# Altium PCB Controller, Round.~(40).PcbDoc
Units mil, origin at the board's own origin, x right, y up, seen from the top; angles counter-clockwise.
Board outline 1800 x 1800 mil, 4 copper layers (Top Layer, MidLayer1, MidLayer2, Bottom Layer); 46 components, 54 nets, 215 pads, 50 vias.
Unrouted connection lines stored in the file: 29.
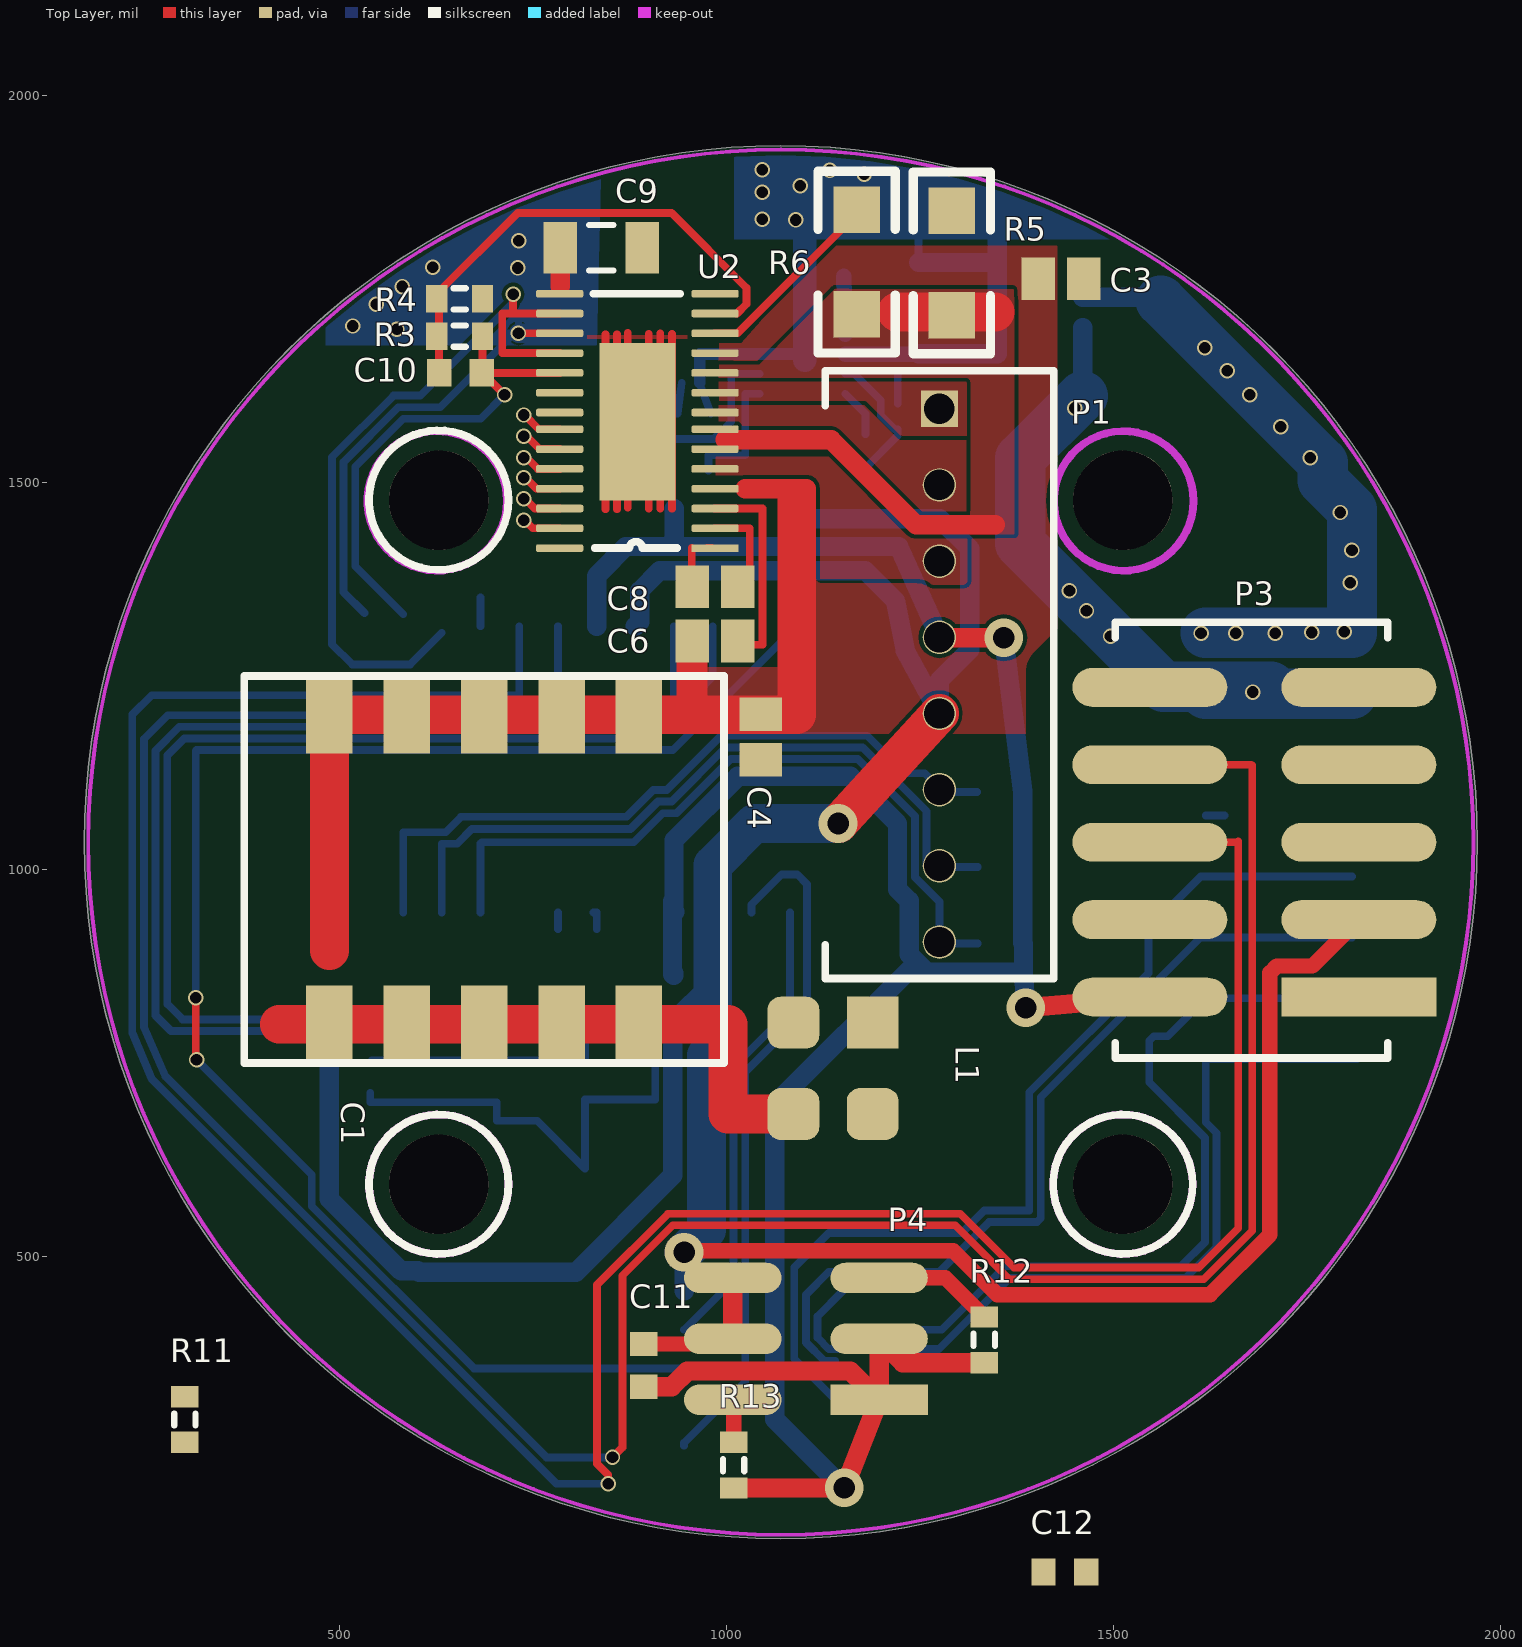
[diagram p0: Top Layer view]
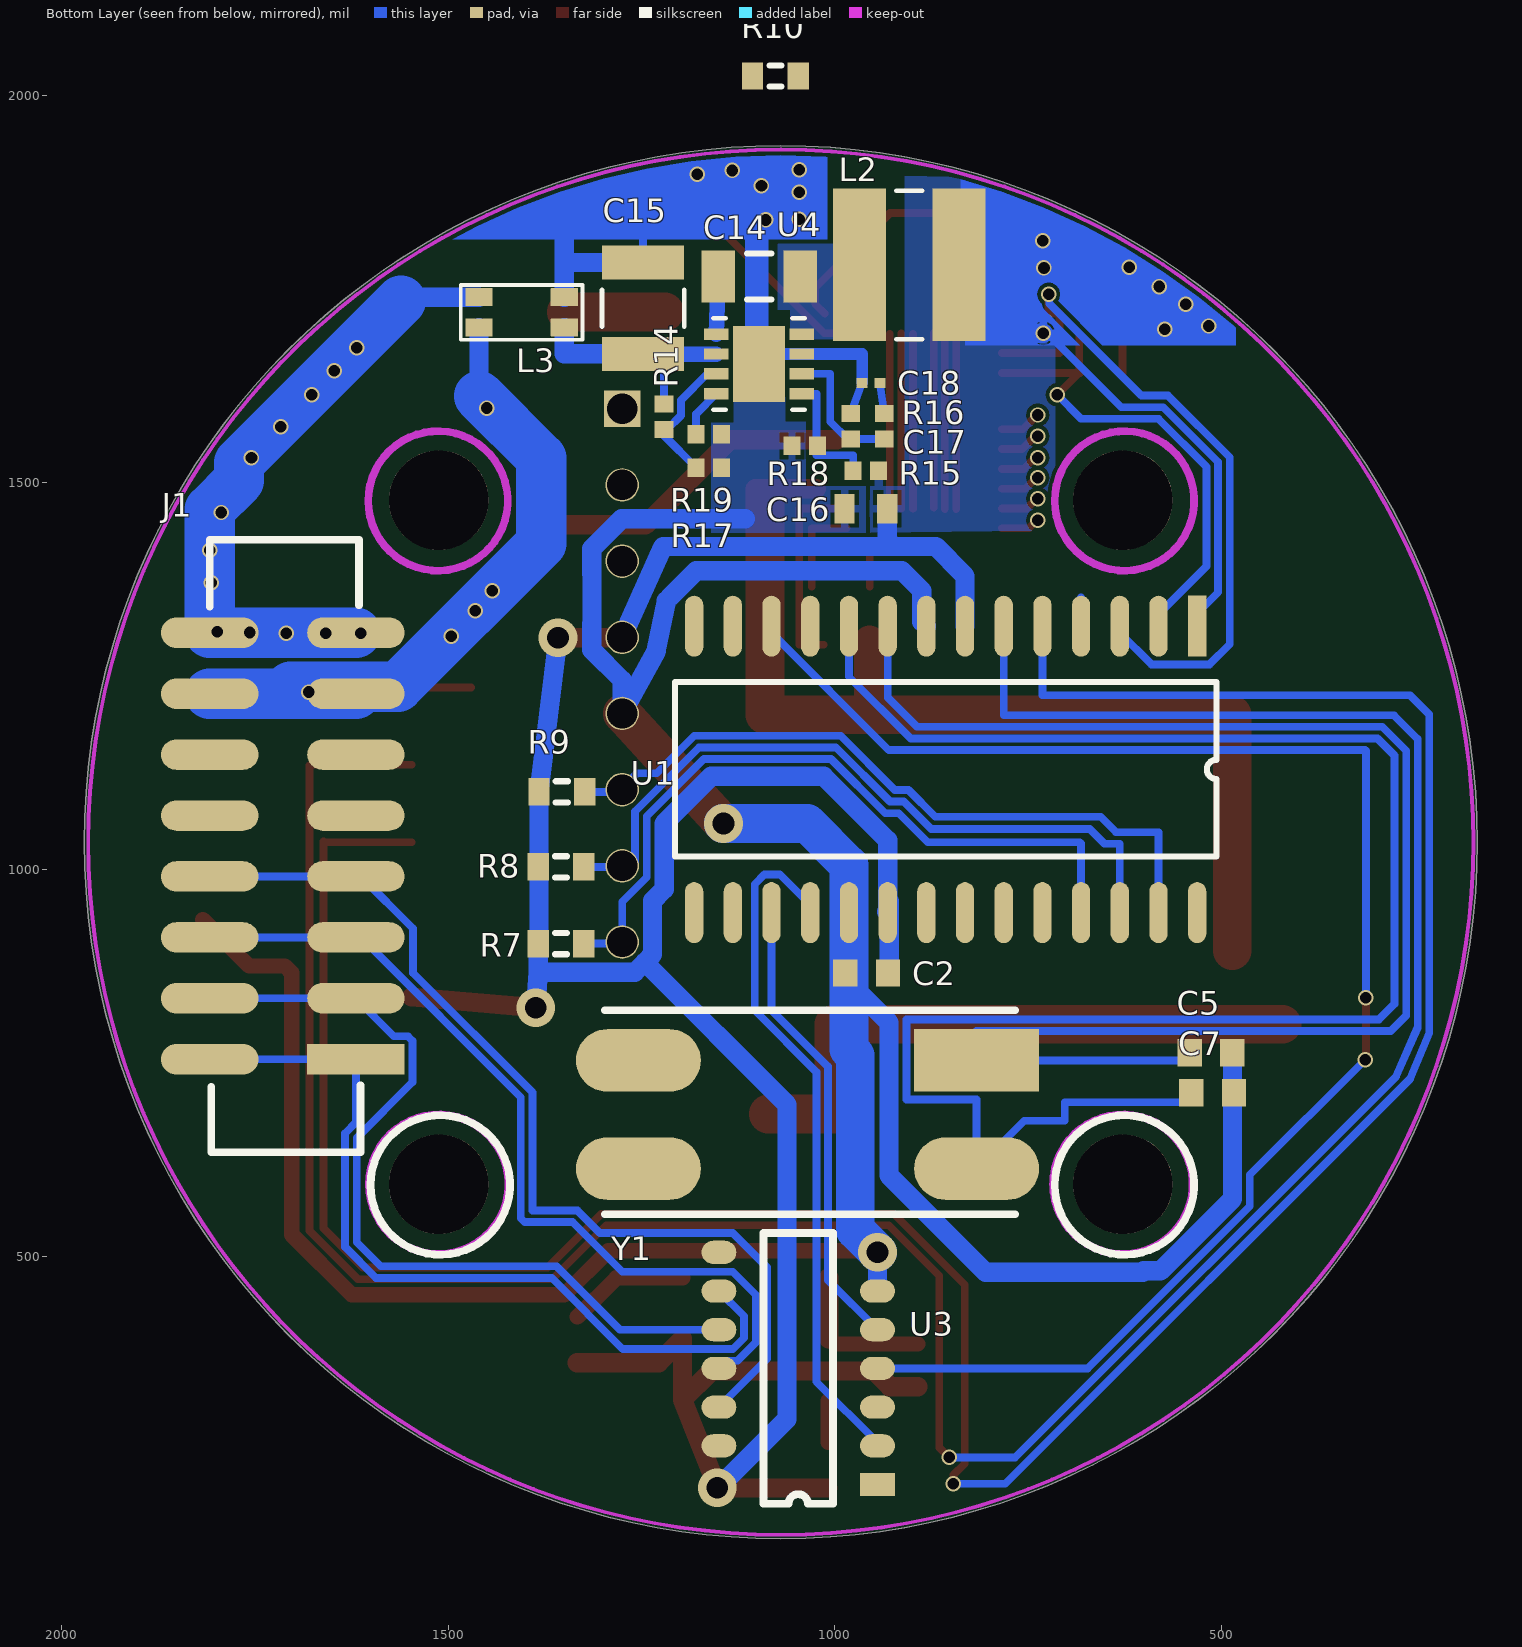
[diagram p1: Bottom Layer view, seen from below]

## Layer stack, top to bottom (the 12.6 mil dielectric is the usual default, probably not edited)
Top Layer: signal copper 1.4
Dielectric: core 12.6, FR-4, Dk 4.8
MidLayer1: signal copper 1.4
Dielectric: prepreg 12.6, FR-4, Dk 4.8
MidLayer2: signal copper 1.4
Dielectric: core 12.6, FR-4, Dk 4.8
Bottom Layer: signal copper 1.4

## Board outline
1070,135 cw(c1070,1035) 170,1035 cw(c1070,1035) 1070,1935 cw(c1070,1035) 1970,1035 cw(c1070,1035)

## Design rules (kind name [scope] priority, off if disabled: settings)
Clearance [All] p1: gap=5
HoleSize [All] p1: absolutevalues=TRUE maxlimit=130 minlimit=15 maxpercent=80.000 minpercent=20.000
MinimumSolderMaskSliver [All] p1: minsoldermaskwidth=5
PolygonConnect PolygonConnect_6 [InComponent('L1') vs InNet('GND')] p1: connectstyle=NoConnect reliefconductorwidth=10 reliefentries=4 polygonreliefangle="90 Angle"
PolygonConnect PolygonConnect_5 [InComponent('L2') vs InNet('VCC')] p2: connectstyle=Direct reliefconductorwidth=10 reliefentries=4 polygonreliefangle="90 Angle"
PolygonConnect PolygonConnect_4 [(InComponent('R19') OR InComponent('R17') OR InComponent('U4')) vs InNet('SGND')] p3: connectstyle=Direct reliefconductorwidth=10 reliefentries=4 polygonreliefangle="90 Angle"
PolygonConnect PolygonConnect_3 [All vs InNet('NetC14_1')] p4: connectstyle=Direct reliefconductorwidth=10 reliefentries=4 polygonreliefangle="90 Angle"
PolygonConnect PolygonConnect_2 [WithinRoom('DontPour1') vs InNet('GND')] p5: connectstyle=NoConnect reliefconductorwidth=10 reliefentries=4 polygonreliefangle="90 Angle"
PolygonConnect PolygonConnect_1 [(InComponent('C1')) vs InNet('GND')] p6: connectstyle=NoConnect reliefconductorwidth=10 reliefentries=4 polygonreliefangle="90 Angle"
PolygonConnect [(InNet('NetP1_1') OR InNet('NetP1_2') OR InNet('NetP1_3') OR InNet('VM') OR InNet('VSENSE')) vs (InNet('NetP1_1') OR InNet('NetP1_2') OR InNet('NetP1_3') OR InNet('VM') OR InNet('VSENSE'))] p7: connectstyle=Direct reliefconductorwidth=10 reliefentries=4 polygonreliefangle="90 Angle"
RoomDefinition Controller [InComponentClass('Controller')] p1 off: confinementstyle=ConfineIn formatcopy=TRUE lockcomponents=FALSE outline -1845,-1985 155,-1985 155,-985 -1845,-985
RoutingVias RoutingVias_1 [(InNet('ADDR_IN') OR InNet('ADDR_OUT'))] p1: holewidth=15 width=20 viastyle="Through Hole" minholewidth=15 minwidth=20 maxholewidth=15 maxwidth=20
RoutingVias [All] p2: holewidth=15 width=20 viastyle="Through Hole" minholewidth=15 minwidth=20 maxholewidth=28 maxwidth=50
SilkscreenOverComponentPads [All] p1: minsilkscreentomaskgap=10
SolderMaskExpansion [All] p1: expansion=4
Width Width_1 [All] p1: maxlimit=100 minlimit=6 preferedwidth=10
Width [InNet('VM')] p2: maxlimit=100 minlimit=20 preferedwidth=40
25 further rules are at their usual default settings.

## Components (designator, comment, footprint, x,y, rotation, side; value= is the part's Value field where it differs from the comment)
C1 "Cap Pol1" CAPSTICK-CS4-5-SMD 486.68,1199.77 r0 top
C2 "Cap Semi" 1608[0603] 959,866 r0 bottom
C3 "Cap Semi" C0805 1432,1763 r180 top
C4 "Cap Semi" C0805 1044,1171 r90 top locked
C5 "Cap Semi" 1608[0603] 514,763.02 r0 bottom
C6 "Cap Semi" C0805 985,1295 r180 top locked
C7 "Cap Semi" 1608[0603] 512,711.02 r0 bottom
C8 "Cap Semi" C0805 985,1365 r180 top locked
C9 "Cap Semi" C1206 838,1803 r180 top locked
C10 "Cap Semi" 1608[0603] 656,1641.38 r180 top locked
C11 "Cap Semi" 1608[0603] 893,359 r270 top
C12 "Cap Semi" 1608[0603] 1437,92 r180 top
C14 "C1005X7R1E103K" C1206 1098,1766 r0 bottom
C15 "C3225X7R2A225K230AB" 1210 1248,1725 r90 bottom
C16 "C1608X5R0J106M" 0603 960,1466 r0 bottom
C17 "C0402C330J5GAC" 0402 979.5,1572.5 r90 bottom
C18 "GRM033R61A472KA01D" 0201 953.5,1628.5 r0 bottom
J1 "M80-8281642" M80-828XXXXDIL 1808,1305.67 r180 bottom
L1 "DLW5BTM501SQ2" DLW5A_5B 1086.3,801.85 r0 top locked
L2 "LPS5030-823MLB" LPS5030 904,1781 r0 bottom
L3 "SRF3216-222Y" SRF3216 1460,1700 r90 bottom
P1 "MKS 1658-6-0-808" MKS_1658_A_KF 1275,1595 r270 top locked
P3 "N2510-6V0C-RB-WD" N2510_SMD 1817,835 r180 top
P4 "M80-8280642" M8082806DIL 1008,472 r0 top locked
R3 "Res3" J1-0603 655,1689 r0 top locked
R4 "Res3" J1-0603 655,1737 r180 top locked
R5 "Res3" 1206 1291,1851 r270 top locked
R6 "Res3" 1206 1168,1717 r90 top locked
R7 "Res3" J1-0603 1354,904 r0 bottom
R8 "Res3" J1-0603 1354,1003 r0 bottom
R9 "Res3" J1-0603 1353,1100 r0 bottom
R10 "Res3" J1-0603 1077,2025 r0 bottom
R11 "Res3" J1-0603 300,289 r90 top
R12 "Res3" J1-0603 1333,392 r90 top
R13 "Res3" J1-0603 1009,230 r90 top
R14 "CRCW0402665KFKED" 0402 1221,1585 r270 bottom
R15 "CRCW040253K6FKED" 0402 960,1515 r0 bottom
R16 "CRCW040246K4FKED" 0402 936.5,1572.5 r270 bottom
R17 "CRCW040242K2FKED" 0402 1163,1519 r180 bottom
R18 "CRCW040210K0FKED" 0402 1039,1547 r0 bottom
R19 "CRCW040280K6FKED" 0402 1163,1562 r180 bottom
U1 "PIC_SERVO_SC" SOP28 532,1314.08 r270 bottom
U2 "DRV8313" HTSSOP28 985,1415 r180 top locked
U3 "LTC2864xSOP" SOP14 945,205 r0 bottom
U4 "TPS54061DRBR" S-PVSON-N8 1098,1653 r180 bottom
Y1 "MA-506 10.0000M-C0" MA506 817,753 r270 bottom

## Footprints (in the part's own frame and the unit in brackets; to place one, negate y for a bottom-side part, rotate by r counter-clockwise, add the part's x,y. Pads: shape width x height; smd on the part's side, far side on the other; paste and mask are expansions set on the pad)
0201 [mil]
  rect 14x13 smd: 1(-11.5,0) 2(11.5,0)
0402 [mil]
  rect 22x24 smd: 1(-16.5,0) 2(16.5,0)
0603 [mil]
  rect 26x38 smd: 1(-27.5,0) 2(27.5,0)
1206 [mil]
  rect 60x60 smd: 1(0,0) 2(135,0)
  silkscreen extent -50,-50 185,50
1210 [mil]
  rect 44x106 smd: 1(-59,0) 2(59,0)
  silkscreen extent -24,-53 24,53
1608[0603] [mm] "Chip Capacitor, Body 1.6x0.8mm, IPC High Density"
  rect 0.8x0.9 smd: 1(-0.7,0) 2(0.7,0)
  body extent -0.87,-0.48 0.87,0.48, height 1.3
C0805 [mm] "Chip Capacitor, Body 2.0x1.3mm, IPC High Density"
  rect 1.1x1.4 smd: 1(-0.75,0) 2(0.75,0)
  body extent -1.1,-0.72 1.1,0.72, height 1.4
C1206 [mm] "Chip Capacitor, Body 3.2x1.6mm, IPC High Density"
  rect 1.1x1.7 smd: 1(-1.35,0) 2(1.35,0)
  silkscreen extent -0.4,-0.75 0.4,0.75, body extent -1.7,-0.9 1.7,0.9, height 1.3
CAPSTICK-CS4-5-SMD [mil]
  rect 60x100 smd: 1(0,0) 1(100,0) 1(200,0) 1(300,0) 1(400,0) 2(0,-400) 2(100,-400) 2(200,-400) 2(300,-400) 2(400,-400)
  silkscreen extent -110,-450 510,50
DLW5A_5B [mm]
  rect 1.7x1.7 smd: 1(2.6,0)
  rrect50% 1.7x1.7 smd: 2(0,0) 3(0,-3) 4(2.6,-3)
HTSSOP28 [mm] "HTTSSOP 28 Pin Package, TI"
  rect 1.55x0.25 smd: 1(0,0)
  rrect50% 1.55x0.25 smd: 2(0,-0.65) 3(0,-1.3) 4(0,-1.95) 5(0,-2.6) 6(0,-3.25) 7(0,-3.9) 8(0,-4.45) 9(0,-5.1) 10(0,-5.75) 11(0,-6.4) 12(0,-7.05) 13(0,-7.7) 14(0,-8.35) 15(5.1,-8.35) 16(5.1,-7.7) 17(5.1,-7.05) 18(5.1,-6.4) 19(5.1,-5.75) 20(5.1,-5.1) 21(5.1,-4.45) 22(5.1,-3.9) 23(5.1,-3.25) 24(5.1,-2.6) 25(5.1,-1.95) 26(5.1,-1.3) 27(5.1,-0.65) 28(5.1,0)
  rect 2.5x5.18 smd: Pad(2.55,-4.15)
  silkscreen extent 1.15,-8.35 4,0
J1-0603 [mm] "Chip Resistor, Body 1.6x0.8mm, IPC High Density"
  rect 0.7x0.9 smd: 1(-0.75,0) 2(0.75,0)
  silkscreen extent -0.2,-0.35 0.2,0.35, body extent -0.85,-0.48 0.85,0.48, height 0.9
LPS5030 [mil]
  rect 68.5x197 smd: 1(-64.25,0) 2(64.25,0)
  silkscreen extent -17,-96 17,96
M80-828XXXXDIL [mm]
  rect 3.2x1 smd: 1(4.8,-14)
  oval 3.2x1 smd: 2(0,-14) 3(4.8,-12) 4(0,-12) 5(4.8,-10) 6(0,-10) 7(4.8,-8) 8(0,-8) 9(4.8,-6) 10(0,-6) 11(4.8,-4) 12(0,-4) 13(4.8,-2) 14(0,-2) 15(4.8,0) 16(0,0)
  silkscreen extent 0,-17.05 4.95,3.05
M8082806DIL [mm] "Harwin 2x3"
  rect 3.2x1 smd: 1(4.8,-4)
  oval 3.2x1 smd: 2(0,-4) 3(4.8,-2) 4(0,-2) 5(4.8,0) 6(0,0)
MA506 [mm]
  rect 2.05x4.1 smd: 1(0,0)
  oval 2.05x4.1 smd: 2(0,-11.1) 3(3.55,-11.1) 4(3.55,0)
  round 0.9 on Bottom Overlay: ""(-0.2,3.15)
  silkscreen extent -1.65,-12.2 5.05,1.26
MKS_1658_A_KF [mm] "Stocko MKS-1658 Shrouded Header Connector"
  rect 1.2x1.2 / inner round 1.2 / far side rect 1.2x1.2 hole 1: 1(0,0)
  round 1.1 hole 1: 2(2.5,0) 3(5,0) 4(7.5,0) 5(10,0) 6(12.5,0) 7(15,0) 8(17.5,0)
  silkscreen extent -1.25,-3.75 18.7,3.75
N2510_SMD [mil]
  rect 200x50 smd: 1(0,0)
  oval 200x50 smd: 2(270.08,0) 3(0,-100) 4(270.08,-100) 5(0,-200) 6(270.08,-200) 7(0,-300) 8(270.08,-300) 9(0,-400) 10(270.08,-400)
  silkscreen extent -37,-484 315,79
S-PVSON-N8 [mm]
  rect 0.805x0.37 smd: 1(-1.402,0.975) 2(-1.402,0.325) 3(-1.402,-0.325) 4(-1.402,-0.975) 5(1.402,-0.975) 6(1.402,-0.325) 7(1.402,0.325) 8(1.402,0.975)
  rect 1.702x2.5 smd paste-1.237: 9(0,0)
  silkscreen extent -1.5,-1.5 1.5,1.5
SOP14 [mil]
  rect 45x30 smd: 1(0,0)
  oval 45x30 smd: 2(0,-50) 3(0,-100) 4(0,-150) 5(0,-200) 6(0,-250) 7(0,-300) 8(205,-300) 9(205,-250) 10(205,-200) 11(205,-150) 12(205,-100) 13(205,-50) 14(205,0)
  silkscreen extent 58,-325 148,25
SOP28 [mm]
  rect 2x0.6 smd: 1(0,0)
  oval 2x0.6 smd: 2(0,-1.27) 3(0,-2.54) 4(0,-3.81) 5(0,-5.08) 6(0,-6.35) 7(0,-7.62) 8(0,-8.89) 9(0,-10.16) 10(0,-11.43) 11(0,-12.7) 12(0,-13.97) 13(0,-15.24) 14(0,-16.51) 15(9.4,-16.51) 16(9.4,-15.24) 17(9.4,-13.97) 18(9.4,-12.7) 19(9.4,-11.43) 20(9.4,-10.16) 21(9.4,-8.89) 22(9.4,-7.62) 23(9.4,-6.35) 24(9.4,-5.08) 25(9.4,-3.81) 26(9.4,-2.54) 27(9.4,-1.27) 28(9.4,0)
  silkscreen extent 1.83,-17.14 7.56,0.63
SRF3216 [mm]
  rect 0.6x0.9 smd: 1(0,0)
  rrect10% 0.6x0.9 smd: 2(0,-2.8) 3(1,-2.8) 4(1,0)
  silkscreen extent -0.4,-3.4 1.4,0.6

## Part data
C1: "Polarized Capacitor (Radial)"
C2 C3 C4 C5 C6 C7 C8 C9 C10 C11 C12: "Capacitor (Semiconductor SIM Model)"
C15: "C3225X7R2A225K23"
C18: "GRM033R61A472KA0"
L1 L3: library part "COMMON MODE CHOKE"
P1: library part "Header 8"
P3: library part "Header 5X2", "Header, 5-Pin, Dual row"
P4: library part "Header 6", "Header, 6-Pin"
R3 R4 R5 R6 R7 R8 R9 R10 R11 R12 R13: "Resistor"
U4: "Imported"
Y1: library part MA-406/MA-505/MA-506

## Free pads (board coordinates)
  round 128.5 hole 128.5: ""(628,593) ""(628,1477) ""(1512,593) ""(1512,1477)

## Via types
v1: diameter 20, hole 15, Top Layer to Bottom Layer, 45 vias
v2: diameter 50, hole 28, Top Layer to Bottom Layer, 5 vias

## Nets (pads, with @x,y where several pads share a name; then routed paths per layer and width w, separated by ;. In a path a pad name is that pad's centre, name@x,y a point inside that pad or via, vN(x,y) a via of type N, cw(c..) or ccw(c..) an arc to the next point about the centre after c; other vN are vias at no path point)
\ENC_A: P3.5
\ENC_B: P3.7
\ENC_INDEX: P3.9
\FAULT: R11.2 U1.3 U2.16 U2.18 | length 962.1
  Top Layer w10: v1(724,1743) 724,1718.15 ; U2.18 710,1666.97 710,1718.15 724,1718.15 ; U2.16@784.21,1718.15 724,1718.15
  Bottom Layer w10: U1.3@632,1305.67 591.03,1264.71 516.05,1264.71 489.94,1290.81 489.94,1532.36 569.64,1612.06 603.91,1612.06 723,1731.15 v1@723,1742
ADDR_IN: J1.9 U1.28 | length 24.4
  Bottom Layer w10: J1.9 J1.9@1643.45,1069.45
ADDR_OUT: J1.10 U1.13
CUR_SENSE: C10.1 R3.2 U1.2 U2.19 | length 636.3
  Top Layer w10: C10.1 C10.1@684.62,1641.38 ; R3.2 684.53,1641.38 C10.1@684.62,1641.38 ; v1(713,1613) C10.1@684.62,1641.38 ; U2.19 C10.1@684.62,1641.38
  Bottom Layer w10: U1.2@582,1329.4 519.94,1391.46 519.94,1519.93 582.07,1582.06 682.06,1582.06 v1(713,1613)
ENC_A: P3.6 U1.5 | length 3676.7
  Top Layer w10: v1(847,206) 847,217.22 832.5,231.72 832.5,463.21 924.29,555 1301.73,555 1371.43,485.31 1610.09,485.31 1661,536.21 1661,1036 1660,1035 P3.6
  Bottom Layer w10: U1.5 732,1225 257,1225 232,1200 232,789 257.03,729.03 780.2,205.87 v1@847.63,205.87
ENC_B: P3.8 U1.6 | length 3755.2
  Top Layer w10: v1(852.5,240) 865.28,252.78 865.28,474.78 930.5,540 1295.52,540 1365.21,470.31 1616.31,470.31 1679,533 1679,1134 1678,1135 P3.8
  Bottom Layer w10: U1.6 782,1199 277.79,1199 247,1168.21 247,796 275,732.28 767.28,240 v1(852.5,240)
ENC_INDEX: P3.10 U1.15 | length 76.5
  Top Layer w10: P3.10@1470.43,1235 P3.10
GND: C1.2 C3.1 C4.1 C9.1 L1.3 R4.1 R5.1 R10.1 U2.14 U2.20 U2.28 U2.Pad | length 2136.2
  Top Layer w10: 843.33,1465.22 843.33,1691.2 ; 858.33,1465.22 858.33,1691.2 ; 872.33,1467.22 872.33,1693.2 ; 899.33,1465.78 899.33,1691.76 ; 914.33,1466.22 914.33,1692.2 ; 929.33,1465.78 929.33,1691.76
  Top Layer w50: 422,799.77 486.68,799.77 586.68,799.77 686.68,799.77 786.68,799.77 886.68,799.77 1001.81,799.77 1001.81,683.74 L1.3
HALL1: P1.8 R7.1 U1.25 | length 951.6
  Bottom Layer w10: U1.25 682,1033.19 683.81,1035 880,1035 917.5,1072.5 935.18,1072.5 1005.18,1142.5 1169.4,1142.5 1243.35,1068.55 1243.35,989.65 1275,958 P1.8 P1.8@1275,904 ; P1.8@1277.02,904 R7.1
HALL2: P1.7 R8.1 U1.26 | length 936.2
  Bottom Layer w10: U1.26 632,1033 651.81,1033 670.81,1052 875.79,1052 911.29,1087.5 928.97,1087.5 998.97,1157.5 1175.61,1157.5 1258.35,1074.76 1258.35,1004.45 P1.7 ; P1.7@1276.45,1003 R8.1
HALL3: P1.6 R9.1 U1.27 | length 928.2
  Bottom Layer w10: U1.27 582,1048 636.81,1048 656.81,1068 870.58,1068 905.08,1102.5 922.75,1102.5 992.75,1172.5 1181.82,1172.5 1230.32,1124 1255.77,1124 1273.35,1106.43 1273.35,1104.53 P1.6 1277.87,1100 R9.1
LIMIT1: P4.2 R13.2 U1.16 | length 54
  Top Layer w20: R13.2 P4.2@1009,313.52
LIMIT2: P4.5 R12.2 U1.14 | length 156.9
  Top Layer w20: P4.5 1282.53,472 R12.2
NetC5_2: C5.2 U1.9 Y1.1 | length 2009.6
  Bottom Layer w10: C5.2@541.56,753 Y1.1 817,791 282,791 262,811 262,1153.21 292.79,1184 894.1,1184 932,1221.9 U1.9
NetC6_1: C6.1 U2.3 | length 269
  Top Layer w10: U2.3 1046.18,1466.18 1046.18,1290 C6.1@1014.53,1290
NetC7_2: C7.2 U1.10 Y1.4 | length 2394.8
  Bottom Layer w10: C7.2 539.56,699.06 702.99,699.06 702.99,675 755.24,675 Y1.4 817,702.65 907.71,702.65 907.71,806 297,806 277,826 277,1147 299,1169 902,1169 982,1249 U1.10
NetC8_1: C8.1 U2.2 | length 120.6
  Top Layer w10: U2.2 1030,1440.59 C8.1@1030,1365
NetC8_2: C8.2 U2.1 | length 55.5
  Top Layer w10: C8.2@955,1365 U2.1@955,1415 ; U2.1@975,1415 U2.1@980.47,1415
NetC9_2: C9.2 U2.15 | length 49.4
  Top Layer w25: 784.85,1753.57 C9.2
NetC10_2: C10.2 R3.1 R4.2 U2.13 | length 623.7
  Top Layer w10: R4.2 625.47,1743.47 730,1848 928.87,1848 1025.51,1751.36 1025.51,1730.3 U2.13@1013.36,1718.15 ; C10.2 R4.2@628.44,1737
NetC14_1: C14.1 L2.2 U4.8
NetC14_2: C14.2 U4.1 | length 74.6
  Bottom Layer w20: C14.2 U4.1
NetC15_1: C15.1 L3.2 R14.1 U4.2 | length 267.8
  Bottom Layer w10: R14.1 1221,1639
  Bottom Layer w20: U4.2 C15.1@1247.8,1665.8
  Bottom Layer w25: C15.1 1349.76,1666 L3.2
NetC17_1: C17.1 R16.2 U4.6 | length 177.4
  Bottom Layer w10: R16.2 C17.1 983.64,1556 1006,1578.36 1006,1640.2 U4.6
NetC18_1: C18.1 R16.1 | length 39.9
  Bottom Layer w10: R16.1 C18.1
NetJ1_13: J1.13 J1.14 L1.1 L3.1 | length 914.2
  Bottom Layer w25: 1460,1611.5 L3.1
  Bottom Layer w65: 1460,1611.5 1379.52,1531.02 1379.52,1420.98 1564.82,1235.67 1703.26,1235.67 1712,1226.93 ; J1.13 1712,1226.93 ; J1.14 1712,1226.93
  other v1: 1680,1229 1496,1301 1465,1334 1443,1360 1450,1596
NetJ1_15: J1.15 J1.16 L1.4 L3.4 | length 823.1
  Bottom Layer w25: L3.4 1556.15,1739.37 1560.76,1734.76
  Bottom Layer w65: 1560.76,1734.76 1770.22,1525.3 1770.22,1502.47 1808,1464.7 v1(1808,1412) J1.16 J1.15
  other v1: 1613,1305 1658,1305 1709,1305 1756,1306 1798,1306.83 1806,1370.3 1793,1461 1754,1532 1716,1572 1676,1613 1647,1644 1618,1674
NetP1_1: P1.1 U2.9
NetP1_2: P1.2 U2.8
NetP1_3: P1.3 U2.5
NetR6_2: R6.2 U2.12 | length 261.6
  Top Layer w10: U2.12 1013.98,1692.56 1172.42,1851 R6.2@1181,1851
NetR14_2: R14.2 R17.1 U4.3 | length 175.7
  Bottom Layer w10: U4.3 1164.89,1640.2 1199,1606.09 1199,1586.36 1216.86,1568.5 R14.2 1221,1560.5 R17.1
NetR15_2: R15.2 R18.1 U4.5 | length 165.9
  Bottom Layer w10: R15.2 976.5,1535 1024,1535 1024,1614.61 U4.5
NetR19_1: R19.1 U4.4 | length 63.5
  Bottom Layer w10: U4.4 1179.5,1588.33 R19.1
NetU1_4: U1.4 U2.24 | length 89.3
  Top Layer w10: v1@739,1532 740,1533 740.28,1533 755.92,1517.36 U2.24
  Bottom Layer w10: U1.4 U1.4@682,1351.27
  other v1: 738,1532
NetU1_11: U1.11 U2.22 | length 53.9
  Top Layer w10: v1(738,1587) 738.94,1587 757.4,1568.54 U2.22
NetU1_12: U1.12 U3.4 | length 2058.6
  Top Layer w10: v1(314,834) 314,754 v1(315,754)
  Bottom Layer w10: v1(314,834) 314,1153 315,1154 930.33,1154 1082,1305.67 U1.12 ; v1(315,754) 463.94,605.06 463.94,564.55 673.49,355 U3.4
NetU1_17: U1.17 U3.5 | length 595.7
  Bottom Layer w10: U3.5 1009,469 1009,745 1082,818 U1.17
NetU1_18: U1.18 U3.2 | length 894.8
  Bottom Layer w10: U3.2 945,259 1024,338 1024,738 1103.81,817.81 1103.81,980.59 1091.03,993.37 1071.37,993.37 1032,954 U1.18
NetU1_21: U1.21 U2.27 | length 49.5
  Top Layer w10: v1@739,1451 749.41,1440.59 U2.27
  other v1: 738,1451
NetU1_22: U1.22 U2.25 | length 76.3
  Top Layer w10: v1@739,1506 740.02,1506 754.25,1491.77 U2.25
  Bottom Layer w10: U1.22@828,944 U1.22 U1.22@832,922.82
  other v1: 738,1506
NetU1_23: U1.23 U2.23 | length 73.3
  Top Layer w10: v1@739,1559.65 741.63,1559.65 758.33,1542.95 U2.23
  Bottom Layer w10: U1.23@782,922.82 U1.23
  other v1: 738,1559.65
NetU1_24: U1.24 U2.26 | length 50.4
  Top Layer w10: v1@739,1478.74 739.55,1478.74 752.1,1466.18 U2.26
  other v1: 738,1478.74
RS422_RX_A: J1.7 J1.8 U3.12 | length 1259.2
  Bottom Layer w10: U3.12 1087.5,367.5 1087.5,485.36 1132.14,530 1303.79,530 1332.85,559.07 1390.94,559.07 1390.94,711.65 1545.15,865.86 1545.15,923.38 1612.48,990.71 J1.7 J1.8
RS422_RX_B: J1.5 J1.6 U3.11 | length 1097.4
  Bottom Layer w10: U3.11@1140,365 1125.93,365 1102.5,388.43 1102.5,450.36 1132.14,480 1275,480 1339.07,544.07 1400.89,544.07 1405.94,549.12 1405.94,705.44 1612.48,911.97 J1.5 J1.6
RS422_TX_A: J1.3 J1.4 U3.10 | length 1089.7
  Bottom Layer w10: U3.10 1277.87,405 1359.87,487 1587,487 1618.06,518.06 1618.06,652.78 1546.03,724.81 1546.03,778.32 1551.89,784.18 1569.97,784.18 J1.3 J1.4
RS422_TX_B: J1.1 J1.2 U3.9 | length 1094
  Bottom Layer w10: U3.9 1117.5,422.5 1117.5,394.64 1132.14,380 1274.09,380 1366.09,472 1593.21,472 1633.06,511.84 1633.06,658.99 1619.02,673.03 J1.1 J1.2 J1.2@1814.55,754.49
SGND: C2.2 C5.1 C7.1 C11.1 C12.2 C15.2 C16.2 C17.2 C18.2 L3.3 P1.5 P3.3 P4.4 P4.6 R10.2 R17.2 R18.2 R19.2 U1.8 U1.19 U3.6 U3.7 U4.7 U4.9 | length 5267.1
  Top Layer w20: C11.1 P4.4@1001.3,386.56 ; v2(945,505) 947,507 1293,507 1349.69,450.31 1624.59,450.31 1702,527.72 1702,866.21 1710.79,875 1757,875 P3.3
  Top Layer w25: P4.4 P4.6
  Top Layer w50: v2@1144.43,1059 P1.5
  Bottom Layer w10: C18.2 C17.2 ; U1.19 U1.19@985,944
  Bottom Layer w15: C18.2 965,1665.8 U4.7 U4.9@1098,1665.8
  Bottom Layer w25: C5.1 486.44,573.87 579.31,481 600.84,481 602.46,479.38 805.31,479.38 930.21,604.27 930.21,802 982,853.79 C2.2@986.5,858.29 ; U1.8 887.69,1319.77 887.69,1359.99 913.65,1385.95 1179.14,1385.95 1211.31,1353.78 1211.31,1353.69 1218,1347 1231,1282 P1.5 1275,1244.35 1314.15,1283.51 1314.15,1317.55 1314,1317.7 1314,1381.78 1314.15,1381.93 1314.15,1414.37 1275.72,1452.8 1116,1452.8 ; U3.6 v2(945,505) ; 1098,1827 1349.76,1827 1349.76,1784 ; C15.2 1349.76,1784 ; L3.3 1349.76,1784 ; C2.2@986.5,858.29 986.56,858.35 C2.2 986.5,865.94 C2.2@986.5,858.29
  Bottom Layer w30: U4.9@1101,1657.8 1101,1819
  Bottom Layer w50: v2(945,505) 974,534 974,759.5 982,767.5 982,853.79 U1.19 982,1005.5 1035.73,1059.23 v2(1144,1059.23)
  other v1: 1089.32,1839 1046.18,1840 1046,1875 1095,1883 1178,1898 1133,1903 1046,1904
VCC: C2.1 C11.2 C12.1 C16.1 L2.1 P1.4 P3.2 P4.1 P4.3 R7.2 R8.2 R9.2 R11.1 R12.1 R13.1 R15.1 U1.1 U1.7 U1.20 U2.17 U3.14 | length 4502.8
  Top Layer w10: v1@731,1692 731.56,1692.56 U2.17
  Top Layer w25: C11.2 929.03,331.44 949.29,351.7 1159.79,351.7 P4.1 ; R13.1 v2@1151.47,200.47 ; v2(1152,201) P4.1 ; P1.4@1275.72,1299 v2(1358,1299) ; R12.1 1227.76,362.47 P4.3 P4.1 ; v2(1386.66,821) P3.2
  Bottom Layer w10: U1.1@532,1331.13 504.94,1358.19 504.94,1526.14 575.86,1597.06 630.06,1597.06 v1@725,1692 ; 803.83,1692.56 805,1691.39
  Bottom Layer w20: U3.14 1150,200.44 v2(1152,201)
  Bottom Layer w25: v1(731,1692.56) 803.83,1692.56 ; U1.7 832,1379 852,1399 852,1399.43 869.57,1417 924,1417 ; C2.1@930,864 930,958.92 U1.20 U1.20@932,946 ; C2.1@931.44,862.9 C2.1 ; U1.20@931.44,946.56 U1.20@932,946 ; C16.1 932.5,1425.5 924,1417 ; U1.20@933,945 U1.20@932,946 ; U3.14 1146.54,205 1062,289.54 1062,696 1245.83,879.83 ; P1.4 1222.31,1417 924,1417 ; v2(1358,1299) R9.2 R7.2@1382.53,905 ; R7.2 1383.53,867.47 1383.56,867 ; v2(1386.66,821) 1383.56,867 ; U1.20@932,946 932,1037.5 1014.5,1120 1160.08,1120 1220.85,1059.23 1220.85,974.16 1235.85,959.16 1235.85,889.81 1245.83,879.83 ; 1245.83,879.83 1258.78,866.87 1291.22,866.87 1291.35,867 1383.56,867
  other v1: 574,1698 517,1702 547,1730 581,1753 730,1777 620,1778 731.56,1812
VM: C1.1 C3.2 C4.2 C6.2 L1.2 U2.4 U2.11 | length 1387.8
  Top Layer w25: 1024,1491.77 1102.89,1491.77 1102.89,1466.75 1101.88,1465.74
  Top Layer w40: 955.47,1200 C6.2
  Top Layer w50: 486.68,895 486.68,1199.77 586.68,1199.77 686.68,1199.77 786.68,1199.77 886.68,1199.77 1090.39,1199.77 1090.39,1478.74
VSENSE: R5.2 R6.1 U2.6 U2.7 U2.10 | length 521.6
  Top Layer w25: 997.92,1555 1135,1555 1245,1445 1347,1445
  Top Layer w50: 1220,1720 1347,1720
pads on no net: J1.11 J1.12 P3.1 P3.4 U2.21 U3.1 U3.3 U3.8 U3.13 Y1. Y1.2 Y1.3

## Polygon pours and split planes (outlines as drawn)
VM on Top Layer "Top Layer-No Net" (solid, pour order 112): 974,1261 1069,1261 1069,1248 1069,1220.31 1066,1220.31 975,1220.31 975,1223
NetP1_3 on Top Layer "Top Layer-No Net" (solid, pour order 66): 986,1533 1163,1533 1261,1436 1311,1436 1311,1362 1305,1356 1304,1357 1109,1357 1109,1484 1093,1509 986,1509
GND on Top Layer "Top Layer-No Net" (solid, pour order 100): 949.38,1690.05 949.38,1685.37 949.38,1690.01 819.88,1690.01 819.99,1690.01 819.99,1685.26 819.99,1685.22 949.38,1685.22
VM on Top Layer "Top Layer-No Net" (solid, pour order 76): 989.93,1652.03 1427,1650 1427,1806 1080,1806 1045,1771 1045,1709 1018.56,1680 990.24,1679.93
VSENSE on Top Layer "Top Layer-No Net" (solid, pour order 72): 989.78,1627 1383,1627 1384,1750 1140,1750 1042,1652 990.24,1652.03
NetP1_1 on Top Layer "Top Layer-No Net" (solid, pour order 60): 989.89,1630 1310,1630 1310,1560 1225,1560 1180,1605 990.24,1605.12
NetP1_2 on Top Layer "Top Layer-No Net" (solid, pour order 64): 989.78,1599.6 1310.61,1599.49 1309.78,1450 1243,1450 1241,1452.14 1129,1571.86 1021,1571 989.93,1570.93
VM on Top Layer "Top Layer-No Net" (solid, pour order 96): 1089.67,1433 1087.44,1174.94 1427,1174.94 1427,1650.24 1377.15,1650.24 1371.74,1433
VSENSE on Top Layer "Top Layer-No Net" (solid, pour order 78): 1315.41,1627 1371.74,1627 1371.74,1433 1366,1433 1315,1433
VCC on Bottom Layer "Top Layer-No Net" (solid, pour order 108): 955,1435 955,1495 910,1495 910,1896 718.15,1893 715.67,1664 715.67,1438
SGND on Bottom Layer "Top Layer-No Net" (solid, pour order 106): 1064,1610 1064,1578.36 1038,1578.36 1038,1495 960,1495 960,1435 1160,1435 1160,1577 1131,1577 1131,1610
NetC14_1 on Bottom Layer "Top Layer-No Net" (solid, pour order 102): 1058,1685 1058,1723 1074,1723 1074,1808 986,1808 986,1685
GND on Top Layer "Top Layer-No Net" (solid, shelved, pour order 116): 1070,140 cw(c1070,1035) 175,1035 cw(c1070,1035) 1070,1930 cw(c1070,1035) 1965,1035 cw(c1070,1035)

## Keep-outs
Keep-Out Layer:
  circle w10: c628,593 r90.15
  circle w10: c1512,593 r90.15
  circle w10: c1513,1476 r90.15
  circle w10: c626,1476 r90.15
  circle w5: c1070,1035 r895

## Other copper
Bottom Layer:
  region net SGND: 1128.04,1920.57 1185.84,1914.88 1243.14,1905.42 1299.7,1892.24 1355.27,1875.38 1409.62,1854.92 1462.52,1830.95 1494.24,1814 1253,1814 1253,1784 1243,1784 1243,1814 1010,1814 1010,1920.38 1011.96,1920.57 1070,1922.48
  region net VCC: 832,1678 831.42,1677.42 731.77,1677.42 736.85,1678.43 741.81,1681.75 745.13,1686.71 745.3,1687.56 716.7,1687.56 716.87,1686.71 720.19,1681.75 725.15,1678.43 730.23,1677.42 683.69,1677.42 730.21,1723.94 732.42,1727.25 733.19,1731.1 734.81,1732.19 738.13,1737.15 739.29,1743 738.13,1748.85 734.81,1753.81 729.85,1757.13 724,1758.29 718.15,1757.13 713.19,1753.81 709.87,1748.85 708.71,1743 709.87,1737.15 711.76,1734.33 654.85,1677.42 482,1677.42 482,1699.57 484.85,1702.24 529.74,1739.08 576.95,1772.91 626.26,1803.58 677.48,1830.95 730.38,1854.92 784.73,1875.38 837.31,1891.33 hole: 736,1706.86 736,1697.56 745.3,1697.56 745.13,1698.41 741.81,1703.37 736.85,1706.69 hole: 726,1706.86 725.15,1706.69 720.19,1703.37 716.87,1698.41 716.7,1697.56 726,1697.56

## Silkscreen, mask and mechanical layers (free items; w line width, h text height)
Top Overlay:
  circle w10: c628,593 r90.15
  circle w10: c628,1477 r90.15
  circle w10: c1512,593 r90.15
Bottom Overlay:
  circle w10: c626,592 r90.15
  circle w10: c1510,592 r90.15
Mechanical 1:
  circle w5: c1512,1477 r64.25
  circle w5: c1512,593 r64.25
  circle w5: c628,593 r64.25
  circle w5: c628,1477 r64.25
  circle w5: c1070,1035 r900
